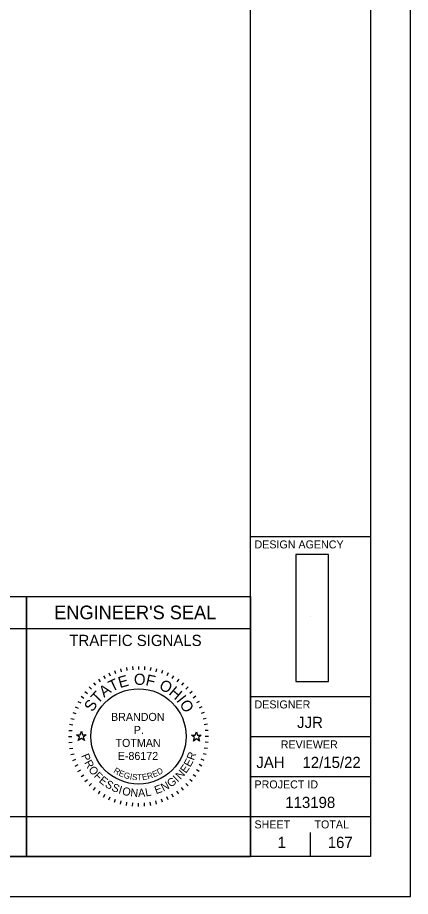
# Model space of a CAD drawing. Extents: x 0 to 34, y 0 to 22.
# Drawn here: x 29.09 to 34, y 0 to 10.99 of the extents above; entities that cross this region are included whole.
import ezdxf

# ---------------------------------------------------------------- set-up
doc = ezdxf.new("R2010")
doc.units = 0
for name, color, linetype in [('GM_X_Adjacent_County', 7, 'Continuous'), ('GM_X_County', 7, 'Continuous'), ('GM_X_Section', 7, 'Continuous'), ('GM_X_Township', 7, 'Continuous')]:
    doc.layers.add(name, color=color, linetype=linetype)

msp = doc.modelspace()

# ---------------------------------------------------------------- linework, layer by layer
at = {"layer": 'GM_X_Adjacent_County'}
msp.add_lwpolyline([(32.977, 2.685), (32.977, 4.275), (32.566, 4.275), (32.566, 2.685)], close=True, dxfattribs=at)
at = {"layer": 'GM_X_County'}
for p, q in [((32, 0.5), (32, 21.5)), ((32, 4.5), (33.5, 4.5)), ((32, 2.5), (33.5, 2.5)), ((32, 2), (33.5, 2)), ((32, 1.5), (33.5, 1.5)), ((32, 1), (33.5, 1))]:
    msp.add_line(p, q, dxfattribs=at)
msp.add_lwpolyline([(1.5, 21.5), (33.5, 21.5), (33.5, 0.5), (1.5, 0.5)], close=True, dxfattribs=at)
at = {"layer": 'GM_X_Section'}
msp.add_lwpolyline([(0, 0), (34, 0), (34, 22), (0, 22)], close=True, dxfattribs=at)
at = {"layer": 'GM_X_Township'}
for p, q in [((26.4, 3.75), (29.2, 3.75)), ((29.2, 3.75), (29.2, 0.5)), ((29.2, 0.5), (29.2, 3.75)), ((29.2, 3.75), (32, 3.75)), ((32, 3.75), (32, 0.5)), ((32.75, 3.5), (32.75, 3.5)), ((26.4, 3.35), (29.2, 3.35)), ((29.2, 3.35), (32, 3.35)), ((30.448, 2.862), (30.455, 2.822)), ((30.524, 2.872), (30.527, 2.832)), ((30.6, 2.875), (30.6, 2.835)), ((30.676, 2.872), (30.673, 2.832)), ((30.752, 2.862), (30.745, 2.822)), ((30.163, 2.758), (30.183, 2.723)), ((30.23, 2.793), (30.247, 2.757)), ((30.301, 2.822), (30.314, 2.785)), ((30.374, 2.845), (30.384, 2.807)), ((30.826, 2.845), (30.816, 2.807)), ((30.899, 2.822), (30.886, 2.785)), ((30.97, 2.793), (30.953, 2.757)), ((31.037, 2.758), (31.017, 2.723)), ((30.038, 2.67), (30.063, 2.64)), ((30.098, 2.717), (30.121, 2.684)), ((31.102, 2.717), (31.079, 2.684)), ((31.162, 2.67), (31.137, 2.64)), ((29.93, 2.562), (29.96, 2.537)), ((29.981, 2.619), (30.01, 2.59)), ((31.219, 2.619), (31.19, 2.59)), ((31.27, 2.562), (31.24, 2.537)), ((29.842, 2.438), (29.877, 2.418)), ((29.883, 2.502), (29.916, 2.479)), ((31.317, 2.502), (31.284, 2.479)), ((31.358, 2.438), (31.323, 2.418)), ((29.807, 2.37), (29.843, 2.353)), ((31.393, 2.37), (31.357, 2.353)), ((29.755, 2.226), (29.793, 2.216)), ((29.778, 2.299), (29.815, 2.286)), ((31.422, 2.299), (31.385, 2.286)), ((31.445, 2.226), (31.407, 2.216)), ((29.738, 2.152), (29.778, 2.145)), ((31.462, 2.152), (31.422, 2.145)), ((29.725, 2), (29.765, 2)), ((29.728, 2.076), (29.768, 2.073)), ((31.472, 2.076), (31.432, 2.073)), ((31.475, 2), (31.435, 2)), ((29.728, 1.924), (29.768, 1.927)), ((31.472, 1.924), (31.432, 1.927)), ((29.738, 1.848), (29.778, 1.855)), ((29.755, 1.774), (29.793, 1.784)), ((31.445, 1.774), (31.407, 1.784)), ((31.462, 1.848), (31.422, 1.855)), ((29.778, 1.701), (29.815, 1.714)), ((31.422, 1.701), (31.385, 1.714)), ((29.807, 1.63), (29.843, 1.647)), ((29.842, 1.563), (29.877, 1.583)), ((31.358, 1.563), (31.323, 1.583)), ((31.393, 1.63), (31.357, 1.647)), ((29.883, 1.498), (29.916, 1.521)), ((29.93, 1.438), (29.96, 1.463)), ((31.27, 1.438), (31.24, 1.463)), ((31.317, 1.498), (31.284, 1.521)), ((29.981, 1.381), (30.01, 1.41)), ((30.038, 1.33), (30.063, 1.36)), ((31.162, 1.33), (31.137, 1.36)), ((31.219, 1.381), (31.19, 1.41)), ((30.098, 1.283), (30.121, 1.316)), ((30.163, 1.242), (30.183, 1.277)), ((30.23, 1.207), (30.247, 1.243)), ((30.301, 1.178), (30.314, 1.215)), ((30.899, 1.178), (30.886, 1.215)), ((30.97, 1.207), (30.953, 1.243)), ((31.037, 1.242), (31.017, 1.277)), ((31.102, 1.283), (31.079, 1.316)), ((30.374, 1.155), (30.384, 1.193)), ((30.448, 1.138), (30.455, 1.178)), ((30.524, 1.128), (30.527, 1.168)), ((30.6, 1.125), (30.6, 1.165)), ((30.676, 1.128), (30.673, 1.168)), ((30.752, 1.138), (30.745, 1.178)), ((30.826, 1.155), (30.816, 1.193)), ((32.75, 0.5), (32.75, 0.8)), ((32.375, 0.675), (32.375, 0.675)), ((26.4, 0.5), (29.2, 0.5)), ((29.2, 0.5), (32, 0.5))]:
    msp.add_line(p, q, dxfattribs=at)
for points in [[(29.824, 2.02), (29.871, 2.02), (29.885, 2.065), (29.899, 2.02), (29.946, 2.02), (29.908, 1.992), (29.923, 1.948), (29.885, 1.975), (29.847, 1.948), (29.862, 1.992)], [(31.263, 2.015), (31.31, 2.015), (31.324, 2.059), (31.339, 2.015), (31.385, 2.015), (31.348, 1.987), (31.362, 1.942), (31.324, 1.97), (31.286, 1.942), (31.301, 1.987)], [(26.4, 0.5), (26.4, 1), (29.2, 1), (29.2, 0.5)], [(29.2, 0.5), (29.2, 1), (32, 1), (32, 0.5)]]:
    msp.add_lwpolyline(points, close=True, dxfattribs=at)
msp.add_circle((30.6, 2), 0.595, dxfattribs=at)

# ---------------------------------------------------------------- texts
for s, height, p in [('DESIGN AGENCY', 0.1, (32.05, 4.35)), ("ENGINEER'S SEAL", 0.17, (29.545, 3.465)), ('TRAFFIC SIGNALS', 0.14, (29.735, 3.13)), ('DESIGNER', 0.1, (32.05, 2.35)), ('BRANDON', 0.1, (30.256, 2.194)), ('JJR', 0.14, (32.583, 2.105)), ('P.', 0.1, (30.54, 2.031)), ('TOTMAN', 0.1, (30.312, 1.869)), ('REVIEWER', 0.1, (32.378, 1.85)), ('E-86172', 0.1, (30.34, 1.706)), ('JAH', 0.14, (32.073, 1.605)), ('12/15/22', 0.14, (32.65, 1.605)), ('PROJECT ID', 0.1, (32.05, 1.35)), ('113198', 0.14, (32.435, 1.105)), ('SHEET', 0.1, (32.05, 0.85)), ('TOTAL', 0.1, (32.8, 0.85)), ('1', 0.14, (32.339, 0.605)), ('167', 0.14, (32.966, 0.605))]:
    msp.add_text(s, height=height, dxfattribs=at).set_placement(p)
for s, height, rotation, p in [('E', 0.14, 15.7571, (30.367, 2.603)), ('O', 0.14, 359.7812, (30.542, 2.644)), ('F', 0.14, 347.4362, (30.681, 2.642)), ('A', 0.14, 36.4747, (30.169, 2.482)), ('T', 0.14, 25.7167, (30.266, 2.554)), ('O', 0.14, 332.2586, (30.846, 2.598)), ('T', 0.14, 46.4344, (30.092, 2.4)), ('H', 0.14, 319.9136, (30.968, 2.532)), ('S', 0.14, 57.1924, (30.026, 2.298)), ('I', 0.14, 308.367, (31.067, 2.447)), ('O', 0.14, 303.1491, (31.106, 2.403)), ('P', 0.1, 291.494, (29.882, 1.762)), ('R', 0.1, 69.2322, (31.291, 1.694)), ('R', 0.1, 298.7311, (29.918, 1.673)), ('E', 0.1, 54.758, (31.193, 1.531)), ('E', 0.1, 61.9951, (31.247, 1.609)), ('O', 0.1, 306.4666, (29.968, 1.585)), ('F', 0.1, 314.7068, (30.034, 1.498)), ('R', 0.075, 327.8239, (30.28, 1.554)), ('E', 0.075, 337.7777, (30.344, 1.513)), ('G', 0.075, 344.2727, (30.408, 1.485)), ('R', 0.075, 17.6836, (30.719, 1.463)), ('E', 0.075, 23.3052, (30.791, 1.486)), ('D', 0.075, 31.466, (30.855, 1.514)), ('N', 0.1, 47.0224, (31.124, 1.455)), ('E', 0.1, 321.4393, (30.097, 1.435)), ('S', 0.1, 328.6764, (30.172, 1.377)), ('I', 0.075, 350.6464, (30.487, 1.463)), ('S', 0.075, 353.7858, (30.515, 1.458)), ('T', 0.075, 3.0061, (30.585, 1.451)), ('E', 0.075, 8.9826, (30.649, 1.453)), ('N', 0.1, 27.3113, (30.91, 1.31)), ('G', 0.1, 35.0469, (31, 1.358)), ('I', 0.1, 43.287, (31.088, 1.422)), ('S', 0.1, 335.9134, (30.254, 1.328)), ('I', 0.1, 343.1505, (30.342, 1.289)), ('O', 0.1, 346.8859, (30.388, 1.274)), ('N', 0.1, 355.1261, (30.495, 1.251)), ('A', 0.1, 2.8617, (30.596, 1.244)), ('L', 0.1, 10.0987, (30.692, 1.249)), ('E', 0.1, 20.0742, (30.82, 1.277))]:
    msp.add_text(s, height=height, rotation=rotation, dxfattribs=at).set_placement(p)

doc.saveas('drawing.dxf')
